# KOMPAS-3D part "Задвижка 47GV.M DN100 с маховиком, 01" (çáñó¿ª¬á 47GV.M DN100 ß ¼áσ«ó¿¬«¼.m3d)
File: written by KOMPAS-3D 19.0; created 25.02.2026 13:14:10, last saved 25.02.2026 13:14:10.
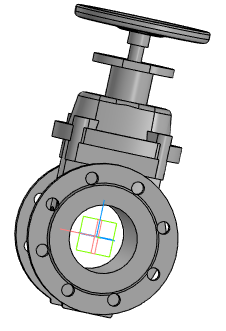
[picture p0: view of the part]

Document properties: Автор: Энергия; Полное имя файла: 47GV.M DN100\Задвижка 47GV.M DN80 с маховиком.a3d

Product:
- Part/product: Задвижка 47GV.M DN100 с маховиком  | designation 01
    Масса: 15.8677
  - Component [detail]: Шпиндель  | pos. 5  | Материал: Сталь 20Х13 ГОСТ 5632 - 2014 (density 7670 kg/m3); Масса: 0.114456; Раздел спецификации: Детали; Форматы листов документа: A3; source file: 47GV.M DN80\DR.47GVM.080.16.00.003 - Шпиндель.cdw, 47GV.M DN80\Шпиндель DN80.m3d
  - Component [assembly]: Клин с направляющими  | designation DR.47GVM.080.16.01.000  | pos. 4  | Раздел спецификации: Сборочные единицы; Форматы листов документа: A4; source file: 47GV.M DN100\DR.47GVM.080.16.01.000 - Клин с направляющими.a3d, 47GV.M DN100\DR.47GVM.080.16.01.000 - Клин с направляющими.spw, 47GV.M DN100\DR.47GVM.080.16.01.000 СБ - Клин с направляющими.cdw
  - Component [detail]: Корпус DN100  | pos. 3  | Материал: ВЧ50 ГОСТ 7293-85 (density 7200 kg/m3); Масса: 12.7287; Раздел спецификации: Детали; Форматы листов документа: 2xA3; source file: 47GV.M DN100\DR.47GV.100.16.00.001 - Корпус.cdw, 47GV.M DN100\DR.47GVM.050.16.00.001 - Корпус.cdw, 47GV.M DN100\DR.47GVM.100.16.00.001 - Корпус.cdw, 47GV.M DN80\Корпус DN80.m3d
  - Component [detail]: Крышка DN100  | pos. 4  | Материал: ВЧ50 ГОСТ 7293-85 (density 7200 kg/m3); Масса: 5.8711; Раздел спецификации: Детали; Форматы листов документа: 2xA3; source file: 47GV.M DN100\DR.47GVM.100.16.00.002 - Крышка.cdw, 47GV.M DN80\Крышка DN80.m3d
  - Component [detail]: Маховик 200  | pos. 15  | Масса: 0.448137; Раздел спецификации: Прочие изделия; source file: ..\..\47GVM\DR.47GVM.100.16.00.000\Маховик 200.m3d
  - Component [standard]: Шайба1021695878  | pos. 20  | Материал: Сталь 12Х18Н10Т ГОСТ 5632-2014 (density 1000 kg/m3); Масса: 0.0121728; Раздел спецификации: Стандартные изделия; Рассекать на разрезах: no; additional columns: ГОСТ 6958-78; A 10.21
  - Component [standard]: Болт М10-6gx20-А2-70 ГОСТ 7798-70  | pos. 12  | Масса: 0.02379; Раздел спецификации: Стандартные изделия; Рассекать на разрезах: no
- Part/product: Задвижка 47GV.M DN100 с маховиком
    Масса: 26.7806
    source file: 47GV.M DN100\DR.47GVM.080.16.00.00 - Задвижка с обрезиненным клином DN80.spw
  - Component: Задвижка с обрезиненным клином DN80. Сборочный чертеж  | designation DR.47GVM.080.16.00.00СБ  | pos. 0  | Масса: 15.8764; Раздел спецификации: Документация; Форматы листов документа: 2xA3; source file: 47GV.M DN100\DR.47GVM.080.16.00.000 СБ - Задвижка с обрезиненным клином DN80.cdw

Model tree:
1. Операция без истории:1

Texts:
  Точка начала. Х
  Точка начала. Y
  Точка начала. Z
